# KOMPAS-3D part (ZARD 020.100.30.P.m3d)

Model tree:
1. Плоскость XY
2. Плоскость ZX
3. Плоскость ZY
4. Ось X
5. Ось Y
6. Ось Z
7. Начало координат
8. Смещенная плоскость:3
     Расстояние = 97
9. Смещенная плоскость:4
     Расстояние = 97
10. Булева операция:1
11. Булева операция:2
12. Булева операция:3
13. Булева операция:4
14. Булева операция:7
15. Булева операция:8
